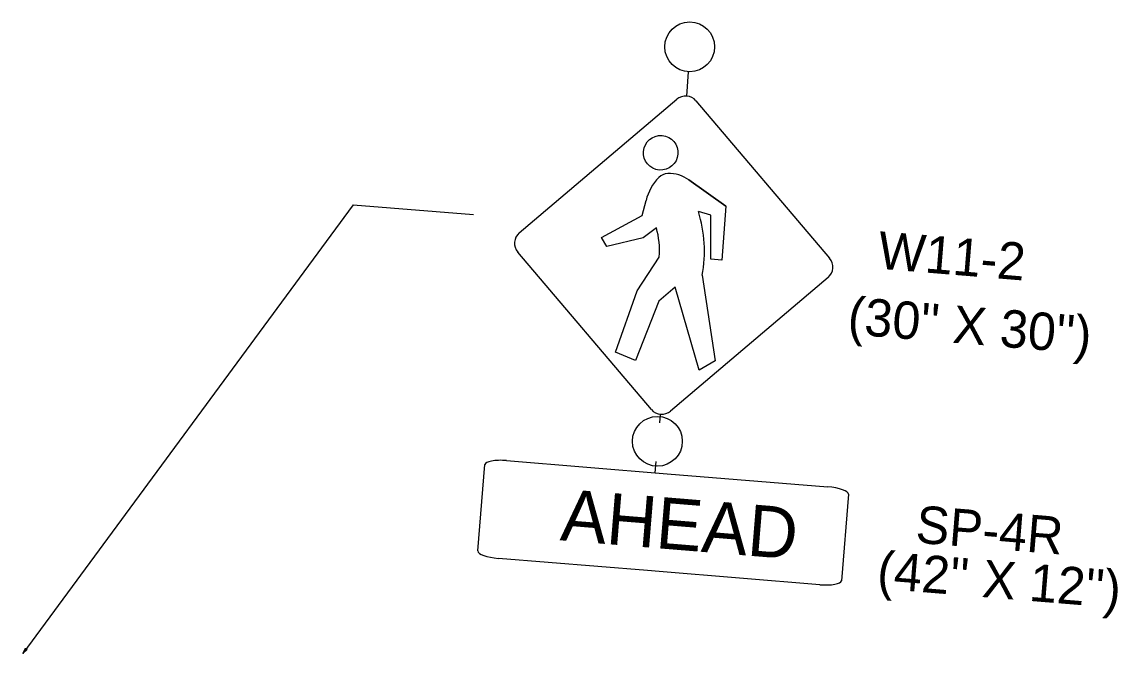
# Model space of a CAD drawing. Extents: x 902965 to 1126554, y 597041 to 686906.
# Drawn here: x 935952.2 to 936040.1, y 681065.2 to 681115.9 of the extents above; entities that cross this region are included whole.
import ezdxf

# ---------------------------------------------------------------- set-up
doc = ezdxf.new("R2010")
doc.units = 0
for name, color, linetype in [('Prop Dimension', 7, 'Continuous'), ('Typical Terminator CELL', 7, 'Continuous'), ('WS SP-4R CELL', 7, 'Continuous'), ('WS W11-2 CELL', 7, 'Continuous')]:
    doc.layers.add(name, color=color, linetype=linetype)

# ---------------------------------------------------------------- blocks, each defined once
blk = doc.blocks.new('TERMINATOR')
at = {"layer": 'Typical Terminator CELL'}
blk.add_lwpolyline([(-0.469, 0.081), (0, 0), (-0.471, -0.083), (-0.411, 0)], close=True, dxfattribs=at)

msp = doc.modelspace()

# ---------------------------------------------------------------- linework, layer by layer
at = {"layer": 'Prop Dimension'}
for p, q in [((936005.471, 681109.988), (936005.627, 681111.939)), ((935978.718, 681101.274), (935988.375, 681100.484)), ((936003.345, 681084.467), (936003.282, 681083.779)), ((936002.997, 681080.676), (936002.914, 681079.773))]:
    msp.add_line(p, q, dxfattribs=at)
msp.add_lwpolyline([(935978.718, 681101.274), (935952.228, 681065.27)], dxfattribs=at)
for centre in [(936005.709, 681113.937), (936003.119, 681082.29)]:
    msp.add_circle(centre, 2, dxfattribs=at)
at = {"layer": 'WS SP-4R CELL'}
for p, q in [((935991.027, 681080.745), (936003.903, 681079.692)), ((936003.903, 681079.692), (936016.779, 681078.638))]:
    msp.add_line(p, q, dxfattribs=at)
for points in [[(935988.722, 681073.493), (935989.289, 681080.427)], [(936018.442, 681078.041), (936017.875, 681071.109)], [(936002.32, 681071.92), (935990.385, 681072.896)], [(936003.261, 681071.843), (936002.331, 681071.919)], [(936016.137, 681070.79), (936003.261, 681071.843)]]:
    msp.add_lwpolyline(points, dxfattribs=at)
for centre, major_axis, start_param, end_param in [((935990.99, 681080.287), (-1.701, 0.139), 4.712162, 6.283185), ((936016.742, 681078.18), (1.701, -0.139), 0, 1.570796), ((935990.423, 681073.354), (-1.701, 0.139), 0, 1.570796), ((936016.174, 681071.247), (-1.701, 0.139), 1.570796, 3.141593)]:
    msp.add_ellipse(centre, major_axis=major_axis, ratio=0.269231, start_param=start_param, end_param=end_param, dxfattribs=at)
at = {"layer": 'WS W11-2 CELL'}
for p, q in [((936005.644, 681103.262), (936008.601, 681101.151)), ((936008.601, 681101.151), (936005.644, 681103.262)), ((936005.644, 681103.262), (936008.601, 681101.151)), ((936001.906, 681100.41), (936002.21, 681101.618)), ((936008.601, 681101.151), (936008.287, 681096.827)), ((935998.64, 681098.633), (936001.906, 681100.41)), ((936007.404, 681100.436), (936006.411, 681100.72)), ((936007.399, 681096.9), (936007.404, 681100.436)), ((936003.036, 681099.421), (936001.992, 681098.611)), ((935999.069, 681097.907), (935998.64, 681098.633)), ((936001.992, 681098.611), (935999.069, 681097.907)), ((936001.503, 681094.375), (936003.268, 681097.076)), ((936008.287, 681096.827), (936007.399, 681096.9)), ((936016.806, 681095.436), (936004.179, 681084.719)), ((936016.806, 681095.436), (936004.179, 681084.719)), ((936006.702, 681095.607), (936007.748, 681088.743)), ((935999.757, 681089.437), (936001.503, 681094.375)), ((936004.533, 681094.655), (936003.223, 681093.543)), ((936006.467, 681087.994), (936004.533, 681094.655)), ((936003.223, 681093.543), (936001.37, 681088.777)), ((936001.37, 681088.777), (935999.757, 681089.437)), ((936007.748, 681088.743), (936006.467, 681087.994))]:
    msp.add_line(p, q, dxfattribs=at)
for points in [[(935992.046, 681099.015), (936004.674, 681109.732)], [(936006.215, 681109.606), (936016.933, 681096.978)], [(936002.637, 681084.845), (935991.92, 681097.473)]]:
    msp.add_lwpolyline(points, dxfattribs=at)
for centre, major_axis, start_param, end_param in [((936005.381, 681108.898), (0.089, 1.09), 6.283072, 7.068583), ((936005.381, 681108.898), (0.089, 1.09), 5.49756, 6.283072), ((936003.99, 681102.72), (-0.086, -1.046), 3.261682, 4.017186), ((936004.055, 681101.037), (0.223, 2.725), 5.744678, 6.403274), ((936006.109, 681100.637), (-0.328, -4.008), 4.017186, 4.547553), ((935996.527, 681097.593), (0.845, 10.332), 4.60131, 5.100443), ((935996.527, 681097.593), (0.551, 6.738), 4.717416, 5.067864), ((935992.754, 681098.181), (0.089, 1.09), 0.785398, 2.356194), ((936016.099, 681096.27), (0.089, 1.09), 3.926991, 5.497787), ((936003.471, 681085.553), (-0.089, -1.09), 5.497787, 6.283185), ((936003.471, 681085.553), (-0.089, -1.09), 6.283185, 7.068583)]:
    msp.add_ellipse(centre, major_axis=major_axis, ratio=0.999996, start_param=start_param, end_param=end_param, dxfattribs=at)
msp.add_ellipse((936003.383, 681105.438), major_axis=(0.113, 1.382), ratio=0.999996, dxfattribs=at)

# ---------------------------------------------------------------- block references
at = {"layer": 'Prop Dimension', "rotation": -126.3440058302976}
msp.add_blockref('TERMINATOR', (935952.228, 681065.27), dxfattribs=at)

# ---------------------------------------------------------------- texts
at = {"layer": 'WS SP-4R CELL'}
for s, height, p in [('AHEAD', 4.125, (935995.264, 681074.357)), ('SP-4R', 3, (936023.76, 681074.166)), ("(42'' X 12'')", 3, (936020.668, 681070.495))]:
    msp.add_text(s, height=height, rotation=355.32222, dxfattribs=at).set_placement(p)
at = {"layer": 'WS W11-2 CELL'}
for s, p in [('W11-2', (936020.726, 681096.15)), ("(30'' X 30'')", (936018.309, 681090.895))]:
    msp.add_text(s, height=3, rotation=355.32222, dxfattribs=at).set_placement(p)

doc.saveas('drawing.dxf')
